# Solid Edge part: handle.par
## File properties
Accuracy: 0.99
Title: Handle
Author: Robert a Rhodes jr
Template: Normal.par
Last saved by: TIET
Revision: 8
Application: Solid Edge
Material: aluminum
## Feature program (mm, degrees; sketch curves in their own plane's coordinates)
sketch for "unnamed RevolvedProtrusion 1" plane through (0, 0, 0) normal (0, -1, 0) x-axis (1, 0, 0)
  line (-87.868, 0.2971) -> (-87.868, -4)
  line (-87.868, -4) -> (-79.868, -4)
  line (-79.868, -4) -> (-79.868, -5)
  line (-79.868, -5) -> (76.132, -5)
  line (76.132, -5) -> (76.132, -4)
  line (76.132, -4) -> (84.132, -4)
  line (84.132, -4) -> (84.132, 0.2971)
revolve "unnamed RevolvedProtrusion 1" add finite 360 deg about sketch line (-87.868, 0.2971) -> (84.132, 0.2971)
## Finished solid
Body 1: solid body, 7 faces, 6 edges, 0 vertices.
  Faces by surface: plane 4, cylinder 3
  Edges by curve: circle 6
Bounding box of the edges (mm): 172.000 x 10.594 x 10.594, from (-87.868, -5.2971, -5) to (84.132, 5.2971, 5.5941).
Cylindrical faces by radius (mm): R4.2971 x2, R5.2971 x1
Planar faces by outward normal: +x 2, -x 2
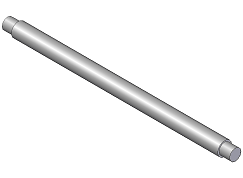
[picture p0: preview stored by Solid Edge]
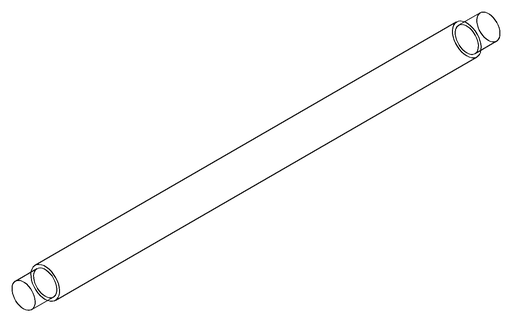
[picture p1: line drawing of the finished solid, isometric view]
